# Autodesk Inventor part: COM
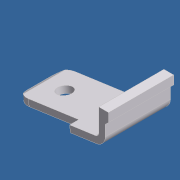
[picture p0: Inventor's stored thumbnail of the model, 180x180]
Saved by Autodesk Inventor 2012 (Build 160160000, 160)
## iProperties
Created: 2008-01
Part Number: COM
Document SubType Name: Modeling
Designer: gstuder
Density: 1 g/cm^3
Material: Default
Author: gstuder
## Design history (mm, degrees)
sketch "Sketch1"
  geometry: L1 (31.75, -2.94)-(31.42, -2.94) reference; L2 (31.42, 0.286)-(31.75, 0.286) reference; L3 (34.29, 10.129)-(34.29, -2.597) reference; L4 (7.62, 12.034)-(32.385, 12.034) reference; L5 (6.35, 7.881)-(6.35, 10.764) reference; L6 (5.08, -0.628)-(5.08, 6.611) reference; L7 (6.35, -1.962)-(6.35, -1.898) reference; L8 (33.02, -3.867)-(8.255, -3.867) reference; L9 (20.066, -3.867)-(20.066, -4.705); L10 (20.066, -4.705)-(19.749, -5.01); L11 (19.749, -5.01)-(19.749, -6.07); L12 (18.874, -7.076)-(10.694, -8.229); L13 (10.605, -7.6)-(18.786, -6.447); L14 (19.114, -6.07)-(19.114, -3.861); L15 (10.138, -7.923)-(10.156, -8.048); L16 (10.694, -8.229)-(10.156, -8.048); L17 (10.605, -7.6)-(10.138, -7.923); L18 (20.066, -3.867)-(19.114, -3.861); C1 r 1.613 at (8.89, 9.494) reference; A1 r 1.613 centre (31.75, -1.327) between (31.75, -2.94) and (31.75, 0.286) reference; A2 r 1.613 centre (31.42, -1.327) between (31.42, 0.286) and (31.42, -2.94) reference; A3 r 1.905 centre (32.385, 10.129) between (34.29, 10.129) and (32.385, 12.034) reference; A4 r 1.27 centre (7.62, 10.764) between (7.62, 12.034) and (6.35, 10.764) reference; A5 r 1.27 centre (6.35, 6.611) between (6.35, 7.881) and (5.08, 6.611) reference; A6 r 1.27 centre (6.35, -0.628) between (5.08, -0.628) and (6.35, -1.898) reference; A7 r 1.905 centre (8.255, -1.962) between (6.35, -1.962) and (8.255, -3.867) reference; A8 r 1.27 centre (33.02, -2.597) between (33.02, -3.867) and (34.29, -2.597) reference; A9 r 1.016 centre (18.733, -6.07) between (18.874, -7.076) and (19.749, -6.07); A10 r 0.381 centre (18.733, -6.07) between (18.786, -6.447) and (19.114, -6.07); 4 further points
  constraints: 20 end point, 9 point on line, 4 point on circle, 4 tangent, 3 parallel, 2 centre point, 2 perpendicular
  dimensions: "d0" = 0.9525 distance between parallel lines of L9 L14; "thick" = 0.635 distance between parallel lines of L14 L11; "d3" = 0.635 distance between parallel lines of L13 L12 (= thick); "d10" = 9.652 distance from line of point (19.749, -6.953) L15; "d11" = 2.54 distance of point (19.114, -6.401) L14.end; "d12" = 3.81 vertical distance of L14.end point (10.102, -7.671); "d13" = 3.0861 vertical distance of L9.start point (19.749, -6.953); "d14" = 0.8382 distance of L9.start L9.end; "d15" = 1.143 vertical distance of L9.start L10.end; "d16" = 14.224 distance between parallel lines of L9 L3; "d17" = 0.508 distance of L12.end point (10.191, -8.3); "d18" = 0.254 distance of L15.end point (10.191, -8.3); "d19" = 0.508 distance of L13.start point (10.102, -7.671); "d20" = 0.254 distance of L15.start point (10.102, -7.671); "d21" = 1.016 radius of A9; "d23" = 0.635 radial gap between concentric circles of A9 A10 (= thick)
extrude "Extrusion1" new body sketch "Sketch1" distance "d24" = 6.35; taper "d25" = 0 deg
sketch "Sketch2"
  geometry: L1 (0, 6.35)-(0, 0) reference; L2 (-8.261, 6.35)-(0, 6.35) reference; L3 (-8.769, 0)-(-2.54, 0); L4 (-2.54, 0)-(-2.54, 0.889); L5 (-2.54, 0.889)-(-7.499, 0.889); L6 (-8.769, 2.159)-(-8.769, 0); L7 (-8.769, 6.35)-(-2.54, 6.35); L8 (-2.54, 6.35)-(-2.54, 5.461); L9 (-2.54, 5.461)-(-7.499, 5.461); L10 (-8.769, 4.191)-(-8.769, 6.35); L11 (-8.261, 0)-(0, 0) reference; L12 (0, 6.35)-(0, 0) reference; L13 (-8.261, 6.35)-(0, 6.35) reference; L14 (-8.261, 6.35)-(-8.261, 0) reference; C1 r 0.698 at (-6.229, 3.175); A1 r 1.27 centre (-7.499, 4.191) between (-7.499, 5.461) and (-8.769, 4.191); A2 r 1.27 centre (-7.499, 2.159) between (-8.769, 2.159) and (-7.499, 0.889)
  constraints: 16 end point, 4 parallel, 4 point on circle, 3 centre point, 2 collinear, 2 horizontal, 2 perpendicular, 2 tangent, 1 equal radius, 1 point on line
  dimensions: "d26" = 4.572 distance between parallel lines of L5 L9; "d27" = 2.54 distance between parallel lines of L1 L8; "d28" = 2.54 distance between parallel lines of L4 L1 (= d27); "d29" = 0.889 distance between parallel lines of L2 L9 (computed from d26); "d31" = 2.286 distance from line of L5 C1.centre; "d32" = 1.397 diameter of C1; "d35" = 1.27 radius of A1; "d37" = 6.22915 distance of L3.start L3.end; "d38" = 2.54 distance from line of L10 C1.centre; "d39" = 1.27 horizontal distance of L10.start L9.end (derived); "d40" = 1.27 horizontal distance of L5.end L6.start
extrude "Extrusion2" cut sketch "Sketch2" stored distance "d43" = 6.35; taper "d44" = 0 deg
body "Solid1"
node "Reference1"
node "Projected Loop1"
